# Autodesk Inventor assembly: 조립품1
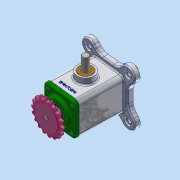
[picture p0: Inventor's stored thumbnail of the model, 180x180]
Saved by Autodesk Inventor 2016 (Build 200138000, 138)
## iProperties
Created: 2019-11
Part Number: 조립품1
Material: 일반
Document SubType Name: Assembly
Designer: user
Author: user
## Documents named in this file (11)
- C:\Users\user\Desktop\491109V1004\조립품1.iam
- C:\Users\user\Desktop\491109V1004\베어링 6203.ipt
- C:\Users\user\Desktop\491109V1004\본체.ipt
- C:\Users\user\Desktop\491109V1004\볼트 M4.ipt
- C:\Users\user\Desktop\491109V1004\부시.ipt
- C:\Users\user\Desktop\491109V1004\스프로킷.ipt
- C:\Users\user\Desktop\491109V1004\슬라이더.ipt
- C:\Users\user\Desktop\491109V1004\오일 실.ipt
- C:\Users\user\Desktop\491109V1004\커버.ipt
- C:\Users\user\Desktop\491109V1004\키 4 x 4 x 14.ipt
- C:\Users\user\Desktop\491109V1004\편심축.ipt
